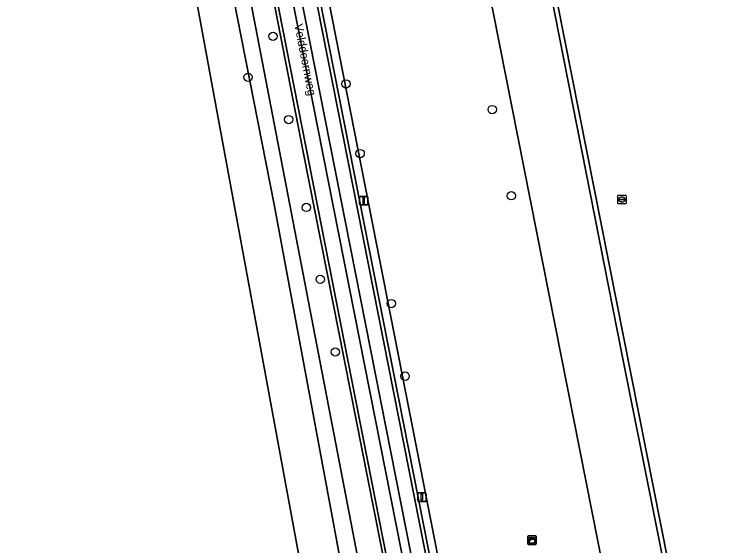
# Model space of a CAD drawing. Extents: x 160203 to 161530, y 379528 to 381797.
# Drawn here: x 160901.9 to 160985.4, y 379790.9 to 379853.2 of the extents above; entities that cross this region are included whole.
import ezdxf

# ---------------------------------------------------------------- set-up
doc = ezdxf.new("R2010")
doc.units = 0
for name, color, linetype in [('IMGEO_Berm_groen', 7, 'Continuous'), ('IMGEO_Berm_open', 7, 'Continuous'), ('IMGEO_Boom', 7, 'Continuous'), ('IMGEO_Grasland_overig', 7, 'Continuous'), ('IMGEO_Groenvoorziening', 7, 'Continuous'), ('IMGEO_Hek', 7, 'Continuous'), ('IMGEO_Kast', 7, 'Continuous'), ('IMGEO_Lichtmast', 7, 'Continuous'), ('IMGEO_Loofbos', 7, 'Continuous'), ('IMGEO_Openbare_ruimte_label', 7, 'Continuous'), ('IMGEO_Rijbaan_lokaal_gesloten', 7, 'Continuous'), ('IMGEO_Rijbaan_lokaal_open', 7, 'Continuous'), ('IMGEO_Waterleidingput', 7, 'Continuous'), ('IMGEO_Waterloop', 7, 'Continuous')]:
    doc.layers.add(name, color=color, linetype=linetype)

msp = doc.modelspace()

# ---------------------------------------------------------------- linework, layer by layer
at = {"layer": 'IMGEO_Berm_groen'}
for points in [[(160958.631, 379721.422), (160935.77, 379837.08), (160928.055, 379876.62)], [(160928.203, 379862.182), (160942.757, 379786.365)]]:
    msp.add_lwpolyline(points, dxfattribs=at)
at = {"layer": 'IMGEO_Berm_open'}
msp.add_lwpolyline([(160977.008, 379644.981), (160931.188, 379877.161), (160922.53, 379920.611), (160921.392, 379926.322), (160920.254, 379932.032), (160919.243, 379931.834), (160920.383, 379926.099), (160921.509, 379920.439), (160930.165, 379876.913), (160975.992, 379644.837)], dxfattribs=at)
at = {"layer": 'IMGEO_Boom'}
for centre in [(160932.237, 379850.616), (160929.308, 379845.817), (160940.789, 379845.036), (160957.932, 379842.034), (160934.075, 379840.853), (160942.452, 379836.874), (160960.175, 379831.915), (160936.141, 379830.555), (160937.777, 379822.114), (160946.105, 379819.279), (160939.541, 379813.597), (160947.716, 379810.762)]:
    msp.add_circle(centre, 0.489, dxfattribs=at)
at = {"layer": 'IMGEO_Grasland_overig'}
msp.add_lwpolyline([(161089.29, 379874.815), (161088.056, 379883.66), (161097.986, 379885.601), (161095.06, 379898.595), (161067.756, 379903.294), (161066.716, 379897.247), (161064.958, 379897.55), (161064.268, 379901.089), (161048.672, 379898.048), (161049.436, 379894.122), (161037.657, 379891.83), (161037.234, 379894.007), (161021.55, 379891.076), (161008.692, 379888.673), (161005.821, 379890.016), (161000, 379888.882), (160960.293, 379881.14), (160984.652, 379758.207), (161001.9, 379671.163), (161088.812, 379688.393), (161124.795, 379695.526), (161114.008, 379750)], close=True, dxfattribs=at)
msp.add_lwpolyline([(160939.886, 379764.635), (160934.912, 379791.637), (160921.698, 379863.365), (160919.535, 379875.796), (160913.862, 379873.11), (160909.876, 379870.503), (160905.47, 379868.825), (160902.112, 379869.215), (160897.347, 379871.132), (160888.883, 379873.232), (160881.959, 379873.681), (160878.062, 379872.662), (160872.07, 379869.972), (160867.612, 379856.511), (160863.25, 379847.506), (160860.404, 379842.34), (160851.931, 379831.925), (160840.36, 379818.697), (160816.73, 379790.123)], dxfattribs=at)
at = {"layer": 'IMGEO_Groenvoorziening'}
for points in [[(161124.795, 379695.526), (161088.812, 379688.393), (161001.9, 379671.163), (160984.652, 379758.207), (160960.293, 379881.14), (160959.816, 379881.047), (160959.923, 379880.506), (160960.044, 379879.897), (160973.148, 379813.39), (160984.112, 379758.571), (160985.826, 379750), (161000, 379678.61), (161001.69, 379670.666), (161089.338, 379688.041), (161125.461, 379695.277), (161122.816, 379708.523), (161121.988, 379712.668), (161114.547, 379750), (161114.008, 379750)], [(160933.003, 379878.977), (160975.515, 379663.394), (160976.372, 379663.386), (160974.152, 379674.687), (160974.084, 379675.034), (160933.995, 379879.074)]]:
    msp.add_lwpolyline(points, close=True, dxfattribs=at)
msp.add_lwpolyline([(160994.949, 379666.912), (160953.018, 379879.004), (160944.827, 379878.526), (160940.522, 379878.685), (160940.034, 379878.68), (160935.083, 379879.181), (160933.995, 379879.074), (160974.084, 379675.034)], dxfattribs=at)
at = {"layer": 'IMGEO_Hek'}
for points in [[(160960.044, 379879.897), (160973.148, 379813.39), (160984.112, 379758.571)], [(160919.378, 379876.7), (160921.698, 379863.365), (160934.912, 379791.637)], [(160934.912, 379791.637), (160939.886, 379764.635)]]:
    msp.add_lwpolyline(points, dxfattribs=at)
at = {"layer": 'IMGEO_Kast'}
for p, q in [((160962.096, 379791.107), (160962.096, 379791.948)), ((160962.096, 379791.948), (160962.096, 379791.107)), ((160962.171, 379792.032), (160963.012, 379792.032)), ((160963.012, 379792.032), (160962.171, 379792.032)), ((160963.096, 379791.957), (160963.096, 379791.116)), ((160963.096, 379791.116), (160963.096, 379791.957)), ((160963.021, 379791.032), (160962.18, 379791.032)), ((160962.18, 379791.032), (160963.021, 379791.032))]:
    msp.add_line(p, q, dxfattribs=at)
for points in [[(160962.291, 379791.822), (160962.891, 379791.822), (160962.891, 379791.737), (160962.291, 379791.737), (160962.291, 379791.822)], [(160962.291, 379791.647), (160962.891, 379791.647), (160962.891, 379791.158), (160962.291, 379791.158), (160962.291, 379791.647)]]:
    msp.add_lwpolyline(points, dxfattribs=at)
msp.add_circle((160962.375, 379791.496), 0.0377, dxfattribs=at)
for centre, start, end in [((160962.174, 379791.954), 92.4484, 184.28452), ((160962.174, 379791.954), 92.4484, 184.28452), ((160963.018, 379791.954), 2.4484, 94.28452), ((160963.018, 379791.954), 2.4484, 94.28452), ((160962.174, 379791.11), 182.4484, 274.28452), ((160962.174, 379791.11), 182.4484, 274.28452), ((160963.018, 379791.11), 272.4484, 4.28452), ((160963.018, 379791.11), 272.4484, 4.28452)]:
    msp.add_arc(centre, 0.0779, start, end, dxfattribs=at)
at = {"layer": 'IMGEO_Lichtmast'}
for p, q in [((160942.368, 379830.939), (160942.368, 379831.739)), ((160942.368, 379831.739), (160942.368, 379830.939)), ((160942.468, 379831.839), (160943.258, 379831.839)), ((160943.258, 379831.839), (160942.468, 379831.839)), ((160943.358, 379831.739), (160943.358, 379830.939)), ((160943.358, 379830.939), (160943.358, 379831.739)), ((160943.258, 379830.839), (160942.468, 379830.839)), ((160942.468, 379830.839), (160943.258, 379830.839)), ((160949.203, 379796.174), (160949.203, 379796.974)), ((160949.203, 379796.974), (160949.203, 379796.174)), ((160949.303, 379797.074), (160950.093, 379797.074)), ((160950.093, 379797.074), (160949.303, 379797.074)), ((160950.193, 379796.974), (160950.193, 379796.174)), ((160950.193, 379796.174), (160950.193, 379796.974)), ((160950.093, 379796.074), (160949.303, 379796.074)), ((160949.303, 379796.074), (160950.093, 379796.074))]:
    msp.add_line(p, q, dxfattribs=at)
for points in [[(160942.788, 379831.714), (160942.938, 379831.714), (160942.938, 379830.964), (160942.788, 379830.964), (160942.788, 379831.714)], [(160949.623, 379796.949), (160949.773, 379796.949), (160949.773, 379796.199), (160949.623, 379796.199), (160949.623, 379796.949)]]:
    msp.add_lwpolyline(points, dxfattribs=at)
for centre, start, end in [((160942.468, 379831.739), 90, 180), ((160942.468, 379831.739), 90, 180), ((160943.258, 379831.739), 0, 90), ((160943.258, 379831.739), 360, 90), ((160942.468, 379830.939), 180, 270), ((160942.468, 379830.939), 180, 270), ((160943.258, 379830.939), 270, 0), ((160943.258, 379830.939), 270, 0), ((160949.303, 379796.974), 90, 180), ((160949.303, 379796.974), 90, 180), ((160950.093, 379796.974), 0, 90), ((160950.093, 379796.974), 360, 90), ((160949.303, 379796.174), 180, 270), ((160949.303, 379796.174), 180, 270), ((160950.093, 379796.174), 270, 0), ((160950.093, 379796.174), 270, 0)]:
    msp.add_arc(centre, 0.1, start, end, dxfattribs=at)
at = {"layer": 'IMGEO_Loofbos'}
for points in [[(160984.112, 379758.571), (160973.148, 379813.39), (160960.044, 379879.897), (160959.923, 379880.506), (160954.03, 379879.063), (160953.018, 379879.004), (160994.949, 379666.912)], [(160932.355, 379830.879), (160923.784, 379874.664), (160923.137, 379877.853)], [(160922.208, 379877.278), (160919.535, 379875.796), (160921.698, 379863.365), (160934.912, 379791.637), (160939.886, 379764.635), (160943.639, 379744.333), (160950.072, 379714.634), (160952.041, 379715.049)], [(160953.39, 379719.069), (160947.233, 379750), (160944.888, 379763.457), (160940.326, 379787.999), (160932.355, 379830.879)]]:
    msp.add_lwpolyline(points, dxfattribs=at)
at = {"layer": 'IMGEO_Rijbaan_lokaal_gesloten'}
for points in [[(160975.992, 379644.837), (160930.165, 379876.913), (160921.509, 379920.439), (160920.383, 379926.099), (160918.669, 379925.757), (160919.788, 379920.148), (160926.309, 379887.469), (160928.422, 379876.713), (160946.014, 379787.182)], [(160975.087, 379663.398), (160924.291, 379920.908), (160923.141, 379926.741), (160921.392, 379926.322), (160922.53, 379920.611), (160931.188, 379877.161), (160977.008, 379644.981)]]:
    msp.add_lwpolyline(points, dxfattribs=at)
at = {"layer": 'IMGEO_Rijbaan_lokaal_open'}
for points in [[(160924.695, 379921.196), (160923.562, 379926.803), (160923.141, 379926.741), (160924.291, 379920.908), (160975.087, 379663.398), (160975.515, 379663.394), (160933.003, 379878.977), (160932.652, 379880.978), (160932.53, 379881.598), (160924.737, 379920.983)], [(160928.422, 379876.713), (160928.174, 379876.677), (160928.055, 379876.62), (160935.77, 379837.08), (160958.631, 379721.422), (160958.762, 379721.914), (160958.699, 379722.306), (160958.858, 379722.379), (160958.424, 379724.606), (160946.014, 379787.182)]]:
    msp.add_lwpolyline(points, close=True, dxfattribs=at)
at = {"layer": 'IMGEO_Waterleidingput'}
for p, q in [((160972.644, 379831.054), (160972.644, 379831.906)), ((160972.719, 379831.98), (160973.571, 379831.98)), ((160973.132, 379831.76), (160973.157, 379831.76)), ((160973.645, 379831.906), (160973.645, 379831.054)), ((160973.571, 379830.98), (160972.719, 379830.98)), ((160972.903, 379831.474), (160972.903, 379831.486)), ((160973.341, 379831.437), (160972.943, 379831.437)), ((160972.946, 379831.523), (160973.344, 379831.523)), ((160973.155, 379831.2), (160973.13, 379831.2)), ((160973.387, 379831.486), (160973.387, 379831.474))]:
    msp.add_line(p, q, dxfattribs=at)
for points in [[(160972.644, 379831.054), (160972.644, 379831.906)], [(160972.719, 379831.98), (160973.571, 379831.98)], [(160973.645, 379831.906), (160973.645, 379831.054)], [(160973.571, 379830.98), (160972.719, 379830.98)]]:
    msp.add_lwpolyline(points, dxfattribs=at)
for centre, radius, start, end in [((160972.721, 379831.904), 0.0765, 91.55205, 178.44795), ((160972.721, 379831.904), 0.0765, 91.55205, 178.44795), ((160973.569, 379831.904), 0.0765, 1.55205, 88.44795), ((160973.569, 379831.904), 0.0765, 1.55205, 88.44795), ((160972.721, 379831.056), 0.0765, 181.55205, 268.44795), ((160972.721, 379831.056), 0.0765, 181.55205, 268.44795), ((160972.943, 379831.483), 0.0403, 85.87752, 175.75265), ((160972.94, 379831.473), 0.0366, 178.93798, 274.71019), ((160973.344, 379831.48), 0.043, 264.86636, 352.45326), ((160973.348, 379831.485), 0.0386, 1.73085, 96.63898), ((160973.569, 379831.056), 0.0765, 271.55205, 358.44795), ((160973.569, 379831.056), 0.0765, 271.55205, 358.44795)]:
    msp.add_arc(centre, radius, start, end, dxfattribs=at)
for centre, major_axis, ratio, start_param, end_param in [((160973.131, 379831.48), (-0.387, 0.002), 0.722429, 4.712389, 7.853982), ((160973.156, 379831.48), (-0.39, 0.002), 0.717154, 1.570796, 4.712389)]:
    msp.add_ellipse(centre, major_axis=major_axis, ratio=ratio, start_param=start_param, end_param=end_param, dxfattribs=at)
at = {"layer": 'IMGEO_Waterloop'}
for points in [[(160923.784, 379874.664), (160932.355, 379830.879), (160940.326, 379787.999)], [(160942.757, 379786.365), (160928.203, 379862.182)]]:
    msp.add_lwpolyline(points, dxfattribs=at)

# ---------------------------------------------------------------- texts
at = {"layer": 'IMGEO_Openbare_ruimte_label'}
msp.add_text('Velddoornweg', height=1, rotation=281.00666, dxfattribs=at).set_placement((160934.724, 379851.979))

doc.saveas('drawing.dxf')
